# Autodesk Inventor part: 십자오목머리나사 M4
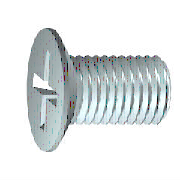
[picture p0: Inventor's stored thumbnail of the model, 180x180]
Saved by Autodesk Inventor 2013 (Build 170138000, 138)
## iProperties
IsCustomPart: 0
Created: 2012-02
Part Number: 십자오목머리나사 M4
Material: 강철, 연강
Description: 십자 오목 머리 나사
Document SubType Name: Modeling
Standard: KS B 1023
Designer: mduedu
Standards Organization: KS
Language: ko-KR
Size Designation: A  M 4 x 12 - H
Categories: <MemberInstance><Categories><Category DisplayName="조임쇠" InternalName="e4da775c-781d-43d5-af7c-5136215cf5a6" Mnemonic="FSTN"><Category DisplayName="볼트" InternalN
Density: 7.86 g/cm^3
Mass: 1.50481 g
Surface Area: 2.78562 cm^2
Volume: 0.191452 cm^3
Author: mduedu
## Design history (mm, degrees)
body "Solid1"
sketch "스케치1"
  geometry: L1 (2.6, 0)-(12, 0); L2 (12, 0)-(12, 2); L3 (12, 2)-(4.1, 2); L4 (4.1, 2)-(3.671, 1.785); L5 (3.671, 1.785)-(2.7, 1.785); L6 (0, 4.2)-(0, 2.4); L7 (0, 2.4)-(1.801, 1.502); L8 (1.801, 1.502)-(2.6, 0); L9 (-2.4, 0)-(14.4, 0) reference; L10 (0, -0.84)-(0, 5.04) reference; L11 (0, 4.2)-(0.285, 4.2); L12 (0.285, 4.2)-(2.7, 1.785); L13 (4.1, 2)-(2.485, 2)
  constraints: 22 end point, 3 parallel, 3 perpendicular, 2 collinear, 1 horizontal, 1 point on line
  dimensions: "d1" = 7.9 distance of L2.end L3.end (= GEL); "d2" = 4 diameter of L3 L1 (= GD); "d3" = 3.57058 diameter of L5 L1 (= BDM); "d4" = 4.8 diameter of L6.end L1 (= SDM); "d5" = 26.5 deg angle of L7 L1; "d6" = 62 deg angle of L8 L1; "d7" = 2.6 distance from line of L1.start L6 (= INTI); "d8" = 0.42941 horizontal distance of L4.end L3.end (= GAL); "d12" = 8.4 diameter of L11 L1 (= KOD); "d13" = 45 deg angle of L12 L1 (= 0.5 x SEWI); "d15" = 12 distance between parallel lines of L2 L6 (= NLG); "d24" = 2.7 distance from line of L5.end L6 (= KOH)
revolve "본체" stored, may be unused: angle "d16" = 90 deg
sketch "스케치2"
  geometry: L1 (0, 2.4)-(0, 0); L2 (0, 0)-(2.4, 0); L3 (0, 0)-(1.697, 1.697); L4 (0.312, 2.38)-(0.408, 0.734); L5 (2.38, 0.312)-(0.734, 0.408); L6 (0, -5.88)-(0, 5.88) reference; L7 (-5.88, 0)-(5.88, 0) reference; L8 (2.38, -0.312)-(0.734, -0.408); L9 (0.312, -2.38)-(0.408, -0.734); L10 (-0.312, -2.38)-(-0.408, -0.734); L11 (-2.38, -0.312)-(-0.734, -0.408); L12 (-2.38, 0.312)-(-0.734, 0.408); L13 (-0.312, 2.38)-(-0.408, 0.734); A1 r 0.72 centre (0, 0) between (0.72, 0) and (0, 0.72); A2 r 0.84 centre (0, 0) between (0.84, 0) and (0, 0.84); A3 r 2.4 centre (0, 0) between (2.38, 0.312) and (0.312, 2.38); A4 r 2.4 centre (0, 0) between (0.312, 2.38) and (0, 2.4); A5 r 2.4 centre (0, 0) between (2.4, 0) and (2.38, 0.312); A6 r 2.4 centre (0, 0) between (0, -2.4) and (0.312, -2.38); A7 r 2.4 centre (0, 0) between (0.312, -2.38) and (2.38, -0.312); A8 r 2.4 centre (0, 0) between (2.38, -0.312) and (2.4, 0); A9 r 2.4 centre (0, 0) between (0, 2.4) and (-0.312, 2.38); A10 r 2.4 centre (0, 0) between (-0.312, 2.38) and (-2.38, 0.312); A11 r 2.4 centre (0, 0) between (-2.38, 0.312) and (-2.4, 0); A12 r 2.4 centre (0, 0) between (-2.4, 0) and (-2.38, -0.312); A13 r 2.4 centre (0, 0) between (-2.38, -0.312) and (-0.312, -2.38); A14 r 2.4 centre (0, 0) between (-0.312, -2.38) and (0, -2.4); A15 r 0.347 centre (0.755, 0.755) between (0.408, 0.734) and (0.734, 0.408); A16 r 0.347 centre (0.755, -0.755) between (0.734, -0.408) and (0.408, -0.734); A17 r 0.347 centre (-0.755, -0.755) between (-0.408, -0.734) and (-0.734, -0.408); A18 r 0.347 centre (-0.755, 0.755) between (-0.734, 0.408) and (-0.408, 0.734); 3 further points
  constraints: 41 point on circle, 22 end point, 22 symmetric about line, 18 centre point, 11 coincident, 4 point on line, 3 tangent, 2 collinear, 1 perpendicular, 1 vertical, 19 other
  dimensions: "d17" = 1.44 diameter of A1 (= 0.3 x SDM); "d18" = 1.68 diameter of A2 (= 0.35 x SDM); "d19" = 4.8 diameter of A3 (= SDM); "d20" = 45 deg angle of L3 L2; "d21" = 0.3115 distance from line of L4.start L1 (= 0.5 x SBR)
extrude "슬롯" join sketch "스케치2" taper "d22" = 5 deg; stored distance "d79" = 25.4
fillet "모깎기1" dims "d23" = 0.1246 (= 0.2 x SBR)
feature "스레드" dims "d10" = 7.9 (= GEL), "d11" = 0
chamfer "모따기1" distance "d25" = 0.42941 (= -0.5 x SPD + 0.5 x GD); stored, may be unused: second distance "d26" = 0.21471 (= 0.5 x GAL), angle "d88" = 45 deg
workplane "Work Plane2"
other parameters: "NLG" = 12 [user parameter; used in 1 equation term], "GEL" = 7.9 [user parameter; used in 2 equation terms], "GAL" = 0.42941 (= 0.61345 x PTC) [user parameter; used in 3 equation terms], "SPD" = 3.14117 (= NND - 1.2269 x PTC) [user parameter; used in 1 equation term], "KOD" = 8.4 [user parameter; used in 1 equation term], "KOH" = 2.7 [user parameter; used in 1 equation term], "SBR" = 0.623 [user parameter; used in 2 equation terms], "INTI" = 2.6 [user parameter; used in 1 equation term], "SDM" = 4.8 [user parameter; used in 5 equation terms], "GD" = 4 (= NND) [user parameter; used in 2 equation terms], "BDM" = 3.57058 (= NND - GAL) [user parameter; used in 1 equation term], "SEWI" = 90 deg [user parameter; used in 1 equation term], "d9" = 4.8 (= SDM), "d27" = 0, "d91" = 0, "d92" = 0, "GUL" = 0.42941 (= 0.61345 x PTC) [user parameter], "TOA" = 30 deg [user parameter], "EPV" = 4.7 [user parameter], "THREADDIA" = 4 [user parameter; used in 1 equation term], "TPU" = 14.28571 (computed from PTC) [user parameter], "PTC" = 0.7 [user parameter; used in 5 equation terms], "NND" = 4 [user parameter; used in 3 equation terms], "GD1" = 3.14117 (= THREADDIA - 1.2269 x PTC) [user parameter]
